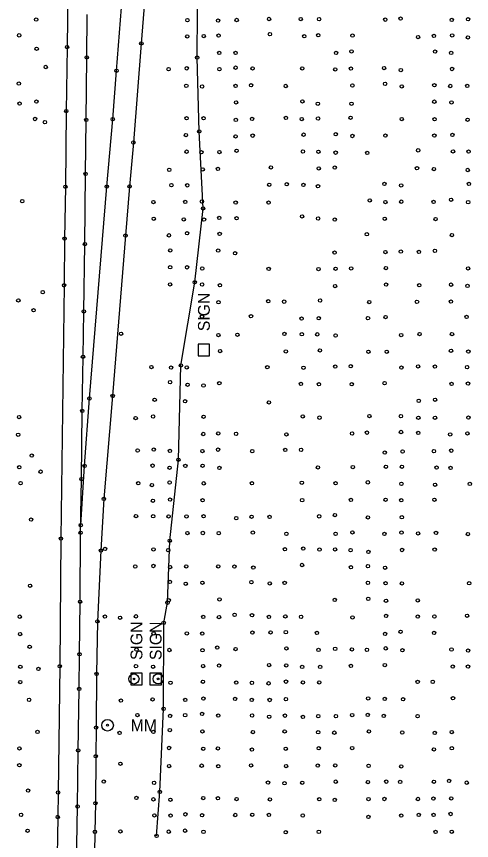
# Model space of a CAD drawing. Extents: x 20503438 to 20508873, y 7964251 to 7984667.
# Drawn here: x 20506665.8 to 20506936, y 7968504.5 to 7968993.7 of the extents above; entities that cross this region are included whole.
import ezdxf

# ---------------------------------------------------------------- set-up
doc = ezdxf.new("R2010")
doc.units = 0
for name, color, linetype in [('SurBreakLine', 7, 'Continuous'), ('SurConcreteSlab', 7, 'Continuous'), ('SurDrainageArrowDown', 7, 'Continuous'), ('SurEdgeRoadPaved', 7, 'Continuous'), ('SurRoadPoints', 7, 'Continuous'), ('SurSurveyPoints', 7, 'Continuous')]:
    doc.layers.add(name, color=color, linetype=linetype)

msp = doc.modelspace()

# ---------------------------------------------------------------- linework, layer by layer
at = {"layer": 'SurBreakLine'}
msp.add_lwpolyline([(20506696.36, 7969009.32), (20506695.84, 7968975.59), (20506695.37, 7968937.58), (20506694.85, 7968892.64), (20506694.37, 7968861.89), (20506694.01, 7968834.14), (20506692.2, 7968683.8), (20506691.46, 7968608.01), (20506690.5, 7968533.02), (20506690.26, 7968518.48), (20506689.75, 7968484.33)], dxfattribs=at)
at = {"layer": 'SurConcreteSlab'}
for points in [[(20506703.95, 7968691.74), (20506706.19, 7968726.95), (20506709.06, 7968766.95), (20506719.37, 7968892.73), (20506722.91, 7968932.79), (20506725.17, 7968961.54), (20506728.11, 7968999.01), (20506731.91, 7969046.15), (20506736.3, 7969102.11), (20506743.28, 7969186.01), (20506746.3, 7969228.05), (20506753.64, 7969313.83), (20506760.75, 7969357.29), (20506767.13, 7969395.55), (20506782.03, 7969476.8), (20506791.56, 7969518.77)], [(20506745.9, 7969054.41), (20506739.91, 7968977.77), (20506735.19, 7968918.92), (20506732.94, 7968892.87), (20506730.52, 7968863.69), (20506722.89, 7968768.43), (20506717.65, 7968707.33), (20506715.93, 7968676.66), (20506713.83, 7968634.58), (20506713.36, 7968603.44), (20506713.02, 7968571.54), (20506712.87, 7968554.57), (20506712.62, 7968526.67), (20506712.33, 7968509.69), (20506711.9, 7968484.13)]]:
    msp.add_lwpolyline(points, dxfattribs=at)
at = {"layer": 'SurDrainageArrowDown'}
msp.add_lwpolyline([(20506748.96, 7968507.26), (20506750.9, 7968533.35), (20506753.16, 7968582.7), (20506753.18, 7968633.77), (20506755.44, 7968645.74), (20506756.79, 7968682.53), (20506761.93, 7968730.56), (20506763.43, 7968786.58), (20506771.63, 7968835.95), (20506776.58, 7968879.79), (20506774.29, 7968925.51), (20506773.07, 7968969.37), (20506773.46, 7969024.17)], dxfattribs=at)
at = {"layer": 'SurEdgeRoadPaved'}
msp.add_lwpolyline([(20506701.3, 7968479.04), (20506702.09, 7968524.73), (20506702.4, 7968557.98), (20506702.99, 7968594.55), (20506703.21, 7968615.13), (20506703.54, 7968646.26), (20506703.87, 7968687.23), (20506704.39, 7968719.09), (20506704.82, 7968759.57), (20506705.28, 7968791.7), (20506705.77, 7968818.66), (20506706.39, 7968858.59), (20506706.81, 7968900.25), (20506707.21, 7968932.32), (20506707.51, 7968969.46), (20506707.84, 7968994.97)], dxfattribs=at)
at = {"layer": 'SurRoadPoints'}
for points in [[(20506780.48, 7968795.7), (20506780.48, 7968795.7), (20506780.48, 7968799.13), (20506773.62, 7968799.13), (20506773.62, 7968792.27), (20506780.48, 7968792.27), (20506780.48, 7968795.7)], [(20506740.46, 7968600.46), (20506740.46, 7968600.46), (20506740.46, 7968603.89), (20506733.6, 7968603.89), (20506733.6, 7968597.03), (20506740.46, 7968597.03), (20506740.46, 7968600.46)], [(20506751.86, 7968600.44), (20506751.86, 7968600.44), (20506751.86, 7968603.87), (20506745, 7968603.87), (20506745, 7968597.01), (20506751.86, 7968597.01), (20506751.86, 7968600.44)]]:
    msp.add_lwpolyline(points, dxfattribs=at)
for centre, radius in [((20506735.55, 7968600.43), 3), ((20506749.89, 7968600.5), 3), ((20506735.55, 7968600.43), 0.5), ((20506749.89, 7968600.5), 0.5), ((20506719.86, 7968572.93), 3.43), ((20506719.86, 7968572.93), 0.571)]:
    msp.add_circle(centre, radius, dxfattribs=at)
at = {"layer": 'SurSurveyPoints'}
for centre in [(20506677.46, 7968991.91), (20506767.3, 7968991.56), (20506796.51, 7968991.65), (20506815.79, 7968992.25), (20506834.53, 7968992.2), (20506845.46, 7968992.15), (20506884.77, 7968991.86), (20506893.81, 7968992.49), (20506924.24, 7968991.74), (20506933.94, 7968992.09), (20506785.51, 7968991.31), (20506667.39, 7968982.55), (20506767.16, 7968981.91), (20506776.95, 7968982.1), (20506785.81, 7968982.37), (20506816.25, 7968983.24), (20506836.67, 7968981.98), (20506844.94, 7968982.6), (20506865.29, 7968982.41), (20506913.64, 7968982.17), (20506924.47, 7968982.54), (20506739.91, 7968977.77), (20506904.24, 7968981.54), (20506933.83, 7968981.32), (20506677.76, 7968974.6), (20506695.84, 7968975.59), (20506786.14, 7968972.11), (20506795.91, 7968972.08), (20506855.51, 7968972.13), (20506864.7, 7968973.01), (20506914.33, 7968972.89), (20506923.88, 7968972.11), (20506707.51, 7968969.46), (20506773.07, 7968969.37), (20506683.16, 7968963.75), (20506756.06, 7968962.46), (20506766.86, 7968962.97), (20506786.24, 7968962.47), (20506795.84, 7968963.35), (20506805.95, 7968962.93), (20506835.47, 7968962.93), (20506855.03, 7968962.29), (20506864.36, 7968962.84), (20506884.06, 7968963.14), (20506924.39, 7968962.57), (20506725.17, 7968961.54), (20506893.99, 7968961.96), (20506667.19, 7968953.91), (20506766.63, 7968952.57), (20506795.89, 7968952.54), (20506805.11, 7968952.89), (20506825.66, 7968952.47), (20506865.21, 7968952.77), (20506884.64, 7968953.76), (20506913.88, 7968952.91), (20506923.36, 7968952.47), (20506933.44, 7968952.5), (20506776.01, 7968952.19), (20506894.54, 7968952.22), (20506677.6, 7968943.21), (20506796.15, 7968942.7), (20506835.57, 7968943.36), (20506913.88, 7968943.17), (20506924.06, 7968942.71), (20506667.59, 7968942.01), (20506844.71, 7968941.94), (20506864.69, 7968941.91), (20506676.81, 7968932.89), (20506695.37, 7968937.58), (20506766.75, 7968933.3), (20506776.89, 7968933.34), (20506805.7, 7968932.94), (20506825.73, 7968933.49), (20506835.13, 7968932.87), (20506844.81, 7968933.18), (20506864.17, 7968933.65), (20506894.51, 7968932.86), (20506682.66, 7968931), (20506707.21, 7968932.32), (20506722.91, 7968932.79), (20506796.01, 7968932.35), (20506914.02, 7968932.73), (20506933.65, 7968932.43), (20506766.42, 7968923.33), (20506774.29, 7968925.51), (20506836.23, 7968923.58), (20506855.33, 7968923.84), (20506924.62, 7968923.41), (20506735.19, 7968918.92), (20506795.87, 7968922.57), (20506806.02, 7968922.99), (20506865.22, 7968922.8), (20506884.85, 7968923), (20506913.88, 7968923.01), (20506766.77, 7968913.48), (20506786.26, 7968913.24), (20506796.5, 7968914.01), (20506835.86, 7968913.59), (20506845.08, 7968913.45), (20506904.29, 7968914.27), (20506924.97, 7968913.66), (20506934.22, 7968913.56), (20506775.55, 7968913.16), (20506855.29, 7968912.9), (20506874.05, 7968912.78), (20506816.85, 7968904.17), (20506845.23, 7968903.52), (20506854.77, 7968904.04), (20506903.58, 7968903.65), (20506706.81, 7968900.25), (20506756.47, 7968902.71), (20506776.36, 7968902.95), (20506785.38, 7968903.23), (20506913.63, 7968903.17), (20506933.69, 7968902.6), (20506815.9, 7968893.84), (20506826.22, 7968894.17), (20506836.17, 7968893.78), (20506884.24, 7968894.34), (20506934.45, 7968894.32), (20506694.85, 7968892.64), (20506719.37, 7968892.73), (20506732.94, 7968892.87), (20506757.74, 7968893.6), (20506767.21, 7968893.51), (20506844.8, 7968892.92), (20506894.19, 7968893.46), (20506669.24, 7968884.09), (20506775.89, 7968883.9), (20506875.55, 7968884.54), (20506923.83, 7968884.92), (20506747.06, 7968883.59), (20506766.02, 7968883.65), (20506776.58, 7968879.79), (20506795.93, 7968883.27), (20506815.45, 7968883.26), (20506884.81, 7968883.53), (20506894.23, 7968883.8), (20506913.45, 7968883.67), (20506933.98, 7968883.5), (20506786.2, 7968874.18), (20506835.33, 7968875.07), (20506747.3, 7968873.69), (20506765.13, 7968873.28), (20506777.11, 7968873.14), (20506796.44, 7968873.93), (20506844.87, 7968873.81), (20506854.77, 7968873.16), (20506884.46, 7968873.66), (20506914.65, 7968873.45), (20506767.05, 7968865.03), (20506786.42, 7968864.63), (20506873.81, 7968864.45), (20506694.37, 7968861.89), (20506730.52, 7968863.69), (20506756.32, 7968863.81), (20506924.29, 7968863.98), (20506706.39, 7968858.59), (20506757.11, 7968854.88), (20506785.53, 7968854.74), (20506914.23, 7968854.6), (20506795.54, 7968853.16), (20506854.65, 7968853.59), (20506884.86, 7968853.84), (20506893.99, 7968854.17), (20506904.72, 7968854), (20506757.04, 7968844.83), (20506767.05, 7968844.82), (20506776.09, 7968844.13), (20506815.52, 7968843.91), (20506845.09, 7968843.77), (20506855.24, 7968843.97), (20506864.5, 7968844.17), (20506885.16, 7968844.38), (20506933.9, 7968844.2), (20506771.63, 7968835.95), (20506681.41, 7968830.07), (20506694.01, 7968834.14), (20506757.01, 7968834.7), (20506775.95, 7968834.62), (20506786.54, 7968834.21), (20506854.93, 7968833.67), (20506885.21, 7968834.61), (20506904.94, 7968834.21), (20506923.79, 7968834.52), (20506933.56, 7968833.75), (20506666.89, 7968825.15), (20506785.73, 7968824.06), (20506815.28, 7968824.68), (20506824.73, 7968824.44), (20506846.02, 7968825.13), (20506875.24, 7968824.18), (20506903.58, 7968824.33), (20506923.74, 7968824.5), (20506675.93, 7968819.33), (20506705.77, 7968818.66), (20506775.94, 7968815.55), (20506805.02, 7968815.79), (20506933.06, 7968815.41), (20506835.04, 7968814.38), (20506845.22, 7968814.59), (20506874.49, 7968814.63), (20506884.91, 7968815.27), (20506727.87, 7968805.38), (20506785.65, 7968804.57), (20506796.96, 7968804.78), (20506824.84, 7968805.28), (20506835.2, 7968805.09), (20506844.33, 7968805.04), (20506855.28, 7968804.35), (20506894.19, 7968804.62), (20506905.12, 7968805.19), (20506924.36, 7968805.19), (20506705.28, 7968791.7), (20506786.66, 7968795.13), (20506825.71, 7968794.87), (20506845.94, 7968795.49), (20506874.75, 7968794.7), (20506885.63, 7968794.72), (20506923.78, 7968795.28), (20506934.07, 7968794.76), (20506763.43, 7968786.58), (20506864.25, 7968786.11), (20506904.21, 7968786.03), (20506745.93, 7968785.59), (20506757.61, 7968785.27), (20506766.84, 7968785.38), (20506814.72, 7968785.53), (20506836.19, 7968785.2), (20506855.02, 7968785.9), (20506894.35, 7968785.31), (20506914.2, 7968785.87), (20506933.32, 7968785.54), (20506757, 7968776.65), (20506767.35, 7968775.11), (20506776.83, 7968774.66), (20506786.22, 7968775.96), (20506834.65, 7968775.61), (20506845.37, 7968775.42), (20506864.83, 7968775.42), (20506884.33, 7968776.06), (20506924.11, 7968775.59), (20506933.87, 7968775.78), (20506709.06, 7968766.95), (20506722.89, 7968768.43), (20506747.82, 7968766.19), (20506765.92, 7968765.28), (20506815.63, 7968764.63), (20506904.59, 7968765.55), (20506914.34, 7968766.19), (20506704.82, 7968759.57), (20506667.31, 7968755.88), (20506736.54, 7968755.29), (20506746.92, 7968756.26), (20506776.9, 7968756.12), (20506835.78, 7968756.29), (20506845.69, 7968755.56), (20506875.3, 7968756.49), (20506894.02, 7968756.46), (20506904.39, 7968755.53), (20506914.28, 7968755.5), (20506934.12, 7968755.64), (20506894.08, 7968747.05), (20506666.78, 7968745.43), (20506776.68, 7968745.86), (20506785.57, 7968746.24), (20506796.15, 7968745.97), (20506826.07, 7968745.63), (20506865.05, 7968746.17), (20506873.89, 7968746.67), (20506904.36, 7968746.52), (20506923.27, 7968745.59), (20506933.51, 7968746.19), (20506674.85, 7968733.07), (20506737.73, 7968736.08), (20506747.31, 7968736.58), (20506756.86, 7968735.82), (20506776.21, 7968735.75), (20506785.49, 7968736.57), (20506805.78, 7968735.68), (20506825.37, 7968736.42), (20506834.77, 7968736.46), (20506884.44, 7968734.81), (20506895.03, 7968735.47), (20506913.62, 7968735.68), (20506923.89, 7968735.98), (20506761.93, 7968730.56), (20506667.46, 7968726.15), (20506680.07, 7968723.5), (20506706.19, 7968726.95), (20506746.56, 7968727.07), (20506756.66, 7968725.81), (20506766.04, 7968726.9), (20506776.3, 7968727.04), (20506786.28, 7968725.75), (20506844.75, 7968726.01), (20506865.49, 7968726.25), (20506885.12, 7968726.43), (20506894.66, 7968726.43), (20506915.2, 7968725.91), (20506923.5, 7968725.74), (20506704.39, 7968719.09), (20506668.21, 7968716.68), (20506738.05, 7968716.65), (20506746.18, 7968715.56), (20506756.66, 7968717.08), (20506776.96, 7968716.57), (20506805.55, 7968716.66), (20506835.21, 7968716.9), (20506855.27, 7968716.59), (20506874.4, 7968717.17), (20506894.33, 7968716.29), (20506914.31, 7968715.72), (20506934.96, 7968716.25), (20506717.65, 7968707.33), (20506746.8, 7968706.26), (20506756.96, 7968706.92), (20506776.29, 7968706.57), (20506835.4, 7968706.59), (20506864.34, 7968706.72), (20506884.93, 7968706.83), (20506894.26, 7968706.53), (20506913.95, 7968706.84), (20506674.46, 7968695.08), (20506736.74, 7968697.16), (20506746.95, 7968697.02), (20506756.11, 7968696.93), (20506766.74, 7968696.96), (20506776.86, 7968697.05), (20506796.3, 7968695.91), (20506805.4, 7968696.72), (20506816.08, 7968696.64), (20506845.5, 7968696.99), (20506854.82, 7968697.73), (20506874.47, 7968696.31), (20506894.57, 7968696.42), (20506703.95, 7968691.74), (20506692.2, 7968683.8), (20506703.87, 7968687.23), (20506767.29, 7968687.04), (20506776.43, 7968687.1), (20506785.84, 7968687), (20506806.11, 7968687.36), (20506826.08, 7968686.6), (20506855.24, 7968686.6), (20506865.24, 7968687.44), (20506884.24, 7968686.56), (20506894.38, 7968687.36), (20506904.2, 7968686.88), (20506914.87, 7968687.13), (20506933.81, 7968686.48), (20506756.79, 7968682.53), (20506715.93, 7968676.66), (20506718.41, 7968677.64), (20506747.15, 7968677.37), (20506755.93, 7968676.9), (20506825.18, 7968677.43), (20506836.04, 7968677.84), (20506845.7, 7968677.27), (20506854.96, 7968677.36), (20506864.16, 7968676.89), (20506874.77, 7968675.87), (20506894.7, 7968677), (20506914.08, 7968677.25), (20506736.27, 7968667.19), (20506747.09, 7968667.51), (20506757.01, 7968666.89), (20506766.56, 7968667.25), (20506785.59, 7968667.24), (20506795.21, 7968667.17), (20506806.41, 7968666.59), (20506835.35, 7968668.09), (20506864.37, 7968666.72), (20506874.41, 7968667.4), (20506884.6, 7968666.49), (20506673.87, 7968655.8), (20506756.87, 7968658.04), (20506766.3, 7968656.94), (20506776.16, 7968657.53), (20506805.26, 7968657.9), (20506816.17, 7968657.17), (20506825.01, 7968657.47), (20506874.47, 7968657.52), (20506884.9, 7968657.28), (20506894.67, 7968657.18), (20506934.56, 7968657.24), (20506703.54, 7968646.26), (20506755.44, 7968645.74), (20506756.21, 7968647.14), (20506786.31, 7968647.7), (20506854.77, 7968647.36), (20506874.63, 7968648.01), (20506885.19, 7968646.89), (20506904.03, 7968647.05), (20506667.71, 7968637.42), (20506713.83, 7968634.58), (20506718.27, 7968637.49), (20506727.3, 7968636.76), (20506736.73, 7968637.61), (20506776.65, 7968637.29), (20506786.03, 7968637.2), (20506795.26, 7968638.5), (20506805.63, 7968638.29), (20506815.67, 7968637.25), (20506825.42, 7968637.56), (20506834.76, 7968637.33), (20506865.29, 7968636.94), (20506885.24, 7968637.86), (20506904.06, 7968637.49), (20506913.93, 7968637.52), (20506933.33, 7968637.98), (20506753.18, 7968633.77), (20506667.92, 7968627.1), (20506747.24, 7968627.47), (20506766.94, 7968627.51), (20506776.09, 7968627.41), (20506805.83, 7968627.99), (20506816.68, 7968628.08), (20506825.71, 7968628.23), (20506844.2, 7968627.75), (20506884.66, 7968627.2), (20506893.81, 7968628.47), (20506913.73, 7968627.79), (20506673.61, 7968619.55), (20506703.21, 7968615.13), (20506737.03, 7968617.89), (20506756.55, 7968617.63), (20506776.23, 7968617.46), (20506785.02, 7968619.07), (20506795.86, 7968618.21), (20506826.08, 7968618.54), (20506845.1, 7968617.65), (20506854.99, 7968618.31), (20506864.98, 7968617.97), (20506873.89, 7968617.72), (20506885.01, 7968618.61), (20506894.93, 7968617.49), (20506924.06, 7968617.94), (20506933.89, 7968617.28), (20506668.06, 7968607.71), (20506678.82, 7968606.38), (20506691.46, 7968608.01), (20506736.74, 7968608.04), (20506746.85, 7968607.66), (20506776.57, 7968608.06), (20506786.09, 7968608.41), (20506815.76, 7968608.68), (20506825.99, 7968608.5), (20506835.4, 7968607.6), (20506846.08, 7968607.57), (20506864.39, 7968608.17), (20506884.48, 7968608.71), (20506924.84, 7968607.75), (20506933.87, 7968607.8), (20506713.36, 7968603.44), (20506668, 7968598.58), (20506757.22, 7968598.2), (20506776.45, 7968598.76), (20506796.27, 7968598.29), (20506805.58, 7968598.15), (20506815.48, 7968597.83), (20506825.81, 7968598.83), (20506835.83, 7968598.37), (20506845.53, 7968598.35), (20506903.98, 7968598.65), (20506912.95, 7968598.74), (20506702.99, 7968594.55), (20506673.24, 7968588.04), (20506727.79, 7968587.57), (20506746.63, 7968588.31), (20506765.99, 7968587.98), (20506776.75, 7968588.75), (20506795.59, 7968588.57), (20506805.46, 7968587.97), (20506816.1, 7968587.95), (20506825.79, 7968588.44), (20506874.59, 7968588.88), (20506884.46, 7968588.59), (20506895.29, 7968588.42), (20506924.96, 7968588.95), (20506753.16, 7968582.7), (20506737.62, 7968579.01), (20506757, 7968578.46), (20506765.93, 7968578.94), (20506775.99, 7968579.69), (20506785.6, 7968578.68), (20506805.66, 7968578.74), (20506815.8, 7968578), (20506825.17, 7968578.65), (20506835.83, 7968577.89), (20506844.98, 7968578.35), (20506855.47, 7968578.36), (20506865.1, 7968578.96), (20506874.36, 7968579.09), (20506883.81, 7968578.52), (20506903.96, 7968578.34), (20506713.02, 7968571.54), (20506678.27, 7968569.01), (20506726.97, 7968568.43), (20506747.04, 7968569.02), (20506756.82, 7968570.12), (20506776.21, 7968569.3), (20506806.18, 7968568.88), (20506825.01, 7968569.26), (20506844.9, 7968568.78), (20506854.51, 7968568.55), (20506875.07, 7968569.32), (20506894.81, 7968568.64), (20506914.14, 7968568.38), (20506924.19, 7968568.87), (20506667.55, 7968559.18), (20506702.4, 7968557.98), (20506756.42, 7968559.45), (20506776.69, 7968559.01), (20506785.35, 7968559.18), (20506805.56, 7968558.51), (20506825.65, 7968559.02), (20506845.23, 7968559.29), (20506865.09, 7968559.43), (20506913.62, 7968558.63), (20506924.26, 7968559.27), (20506712.87, 7968554.57), (20506667.48, 7968549.23), (20506727.47, 7968550.12), (20506756.38, 7968548.69), (20506775.73, 7968548.95), (20506785.55, 7968548.62), (20506805.09, 7968549.09), (20506825.86, 7968548.73), (20506844.65, 7968549.03), (20506855.04, 7968549.11), (20506874.82, 7968548.87), (20506894.24, 7968548.5), (20506717.58, 7968539.5), (20506747.51, 7968538.78), (20506815.12, 7968538.92), (20506824.92, 7968538.5), (20506835.48, 7968538.83), (20506855.33, 7968539.45), (20506874.42, 7968539.22), (20506885.36, 7968539.47), (20506893.59, 7968539.28), (20506913.67, 7968539.4), (20506922.62, 7968539.92), (20506933.15, 7968538.86), (20506672.66, 7968534.17), (20506690.5, 7968533.02), (20506750.9, 7968533.35), (20506736.97, 7968529.8), (20506747.06, 7968528.97), (20506757.2, 7968528.7), (20506776.69, 7968529.74), (20506785.38, 7968529.58), (20506796.45, 7968529.1), (20506816.26, 7968528.95), (20506845.57, 7968528.99), (20506854.73, 7968528.66), (20506874.8, 7968529.09), (20506884.24, 7968529.17), (20506904.15, 7968529.16), (20506913.36, 7968529.41), (20506923.94, 7968529.52), (20506702.09, 7968524.73), (20506712.62, 7968526.67), (20506668.53, 7968519.78), (20506690.26, 7968518.48), (20506747.7, 7968519.41), (20506757.26, 7968519.29), (20506766.08, 7968520.07), (20506776, 7968519.51), (20506795.69, 7968519.67), (20506805.75, 7968519.82), (20506815.67, 7968519.7), (20506835.76, 7968519.37), (20506874.77, 7968518.52), (20506894.23, 7968519.32), (20506904.61, 7968519.75), (20506913.4, 7968519.72), (20506923.54, 7968520.27), (20506672.4, 7968510.35), (20506712.33, 7968509.69), (20506727.47, 7968509.91), (20506748.96, 7968507.26), (20506756.19, 7968509.77), (20506765.89, 7968510.36), (20506776.82, 7968509.68), (20506825.66, 7968509.44), (20506845.3, 7968509.67), (20506914.61, 7968509.6), (20506924.22, 7968509.76)]:
    msp.add_circle(centre, 1, dxfattribs=at)

# ---------------------------------------------------------------- texts
at = {"layer": 'SurRoadPoints'}
for s, rotation, p in [('SIGN', 90, (20506780.55, 7968806.91)), ('SIGN', 90, (20506740.53, 7968611.67)), ('SIGN', 90, (20506751.93, 7968611.65)), ('MM', 360, (20506733.57, 7968569.43))]:
    msp.add_text(s, height=6.995, rotation=rotation, dxfattribs=at).set_placement(p)

doc.saveas('drawing.dxf')
